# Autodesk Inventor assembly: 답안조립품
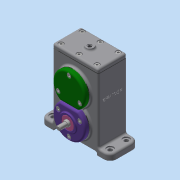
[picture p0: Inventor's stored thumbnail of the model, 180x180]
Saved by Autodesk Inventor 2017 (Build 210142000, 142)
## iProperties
Part Number: 답안조립품
Material: 일반
Document SubType Name: Assembly
Designer: mrc
Author: mrc
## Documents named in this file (24)
- C:\Users\mrc\Desktop\600506V1023\답안조립품.iam
- C:\Users\mrc\Desktop\600506V1023\본체.ipt
- C:\Users\mrc\Desktop\600506V1023\개스킷 A.ipt
- C:\Users\mrc\Desktop\600506V1023\개스킷 B.ipt
- C:\Users\mrc\Desktop\600506V1023\개스킷 C.ipt
- C:\Users\mrc\Desktop\600506V1023\베어링 6001.ipt
- 베어링 6001.ipt
- C:\Users\mrc\Desktop\600506V1023\베어링 6002.ipt
- 베어링 6002.ipt
- C:\Users\mrc\Desktop\600506V1023\볼트 M4.ipt
- C:\Users\mrc\Desktop\600506V1023\스퍼기어 A.ipt
- C:\Users\mrc\Desktop\600506V1023\스퍼기어 B.ipt
- C:\Users\mrc\Desktop\600506V1023\오일 실 10 20 7.ipt
- C:\Users\mrc\Desktop\600506V1023\오일 실 12 22 7.ipt
- C:\Users\mrc\Desktop\600506V1023\축 A.ipt
- C:\Users\mrc\Desktop\600506V1023\축 B.ipt
- C:\Users\mrc\Desktop\600506V1023\칼라.ipt
- C:\Users\mrc\Desktop\600506V1023\커버 A.ipt
- C:\Users\mrc\Desktop\600506V1023\커버 B.ipt
- C:\Users\mrc\Desktop\600506V1023\커버 C.ipt
- C:\Users\mrc\Desktop\600506V1023\커버 D.ipt
- C:\Users\mrc\Desktop\600506V1023\커버 E.ipt
- C:\Users\mrc\Desktop\600506V1023\키 4 x 4 x 12.ipt
- C:\Users\mrc\Desktop\600506V1023\키 5 x 5 x 12.ipt
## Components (5 placed, 3 different names)
1. 개스킷 A:1
2. 개스킷 B:1
3. 개스킷 C:1
4. 개스킷 B:2
5. 개스킷 B:3
